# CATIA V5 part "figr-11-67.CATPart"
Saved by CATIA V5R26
Part number: Part2
Bounding box of the stored display mesh (mm): x -69 to 69, y -70.588 to 84.546, z -60.219 to 83.037
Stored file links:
  D:\_Deepak\CATIA\CATIA V5-6R2016_Deepak\Resources\Part files\Partfiles\c11_catia_v5_6r2016_prt\figr-11-67.CATPart
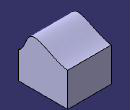
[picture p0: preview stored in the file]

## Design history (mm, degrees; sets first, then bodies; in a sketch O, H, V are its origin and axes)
Set1
  Extrude1: Element1 Sketch2, Lim1 134, Lim2 101, Direction yz-plane
Body1 (main body)
  Sketch1 on yz-plane, origin (0, 0, 0), H (0, 1, 0), V (0, 0, 1)
    line L1 (-70.5879, 56.2311) -> (84.546, 56.2311)
    line L2 (84.546, 56.2311) -> (84.546, -60.2191)
    line L3 (84.546, -60.2191) -> (-70.5879, -60.2191)
    line L4 (-70.5879, -60.2191) -> (-70.5879, 56.2311)
    horizontal: L1 H, L3 H
    vertical: L2 V, L4 V
  Pad1: profile Sketch1, direction (1, 0, 0), length 69, mirrored extent
  SewSurface1: SewingRemoveFace face of Pad1, SplitPlane Extrude1
  Sketch2 on yz-plane, origin (0, 0, 0), H (0, 1, 0), V (0, 0, 1)
    spline S1 through (-101.2957, 16.3509) (-51.8443, 49.0526) (-38.418, 74.5863) (34.1283, 62.9515) (100.0993, 49.0526)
